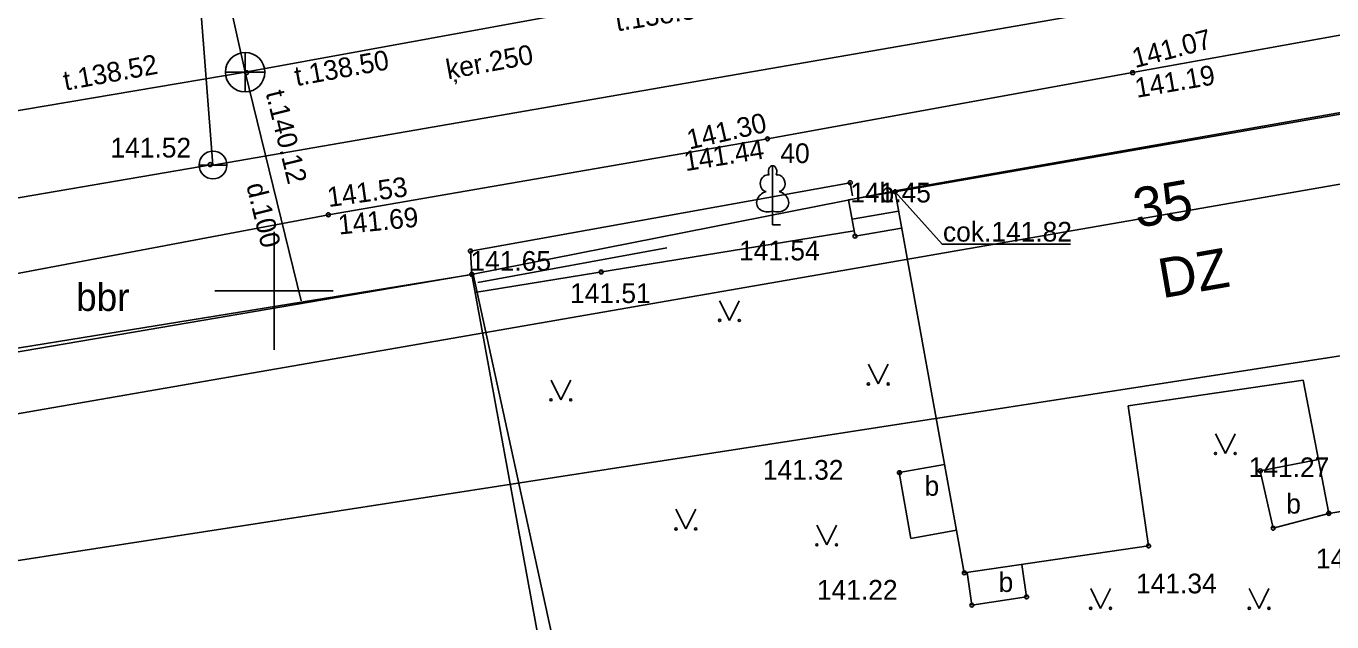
# Model space of a CAD drawing. Extents: x 728492 to 729038, y 272968 to 273171.
# Drawn here: x 728843.71 to 728876.83, y 273091.6 to 273106.71 of the extents above; entities that cross this region are included whole.
import ezdxf

# ---------------------------------------------------------------- set-up
doc = ezdxf.new("R2010")
doc.units = 0
for name, color, linetype in [('APGR_SARK_####_####_#', 7, 'Continuous'), ('BUVE_BDET_####_####_#', 7, 'Continuous'), ('BUVE_BDET_####_TKST_#', 7, 'Continuous'), ('BUVE_EKAS_####_####_#', 7, 'Continuous'), ('BUVE_EKAS_ADRS_TKST_#', 7, 'Continuous'), ('BUVE_EKAS_RAKS_TKST_#', 7, 'Continuous'), ('CELI_CAPM_####_####_#', 7, 'Continuous'), ('CELI_CMAL_####_####_#', 7, 'Continuous'), ('CELI_CSEG_####_TKST_#', 7, 'Continuous'), ('GEOD_ELEM_####_####_#', 7, 'Continuous'), ('NORB_ZOGS_ZSTP_####_#', 7, 'Continuous'), ('RAMI_UZMR_####_####_#', 7, 'Continuous'), ('RELJ_AATZ_####_TKST_#', 7, 'Continuous'), ('RELJ_ELEM_####_####_#', 7, 'Continuous'), ('ROBZ_UZMR_####_####_#', 7, 'Continuous'), ('SKAN_ELEM_####_####_#', 7, 'Continuous'), ('SKAN_VADP_PAST_####_#', 7, 'Continuous'), ('SKAN_VADP_PAST_TKST_#', 7, 'Continuous'), ('TERT_DIAM_####_TKST_#', 7, 'Continuous'), ('TERT_DZOG_####_####_#', 7, 'Continuous'), ('TERT_ELEM_####_####_#', 7, 'Continuous'), ('UDTK_ELEM_####_####_#', 7, 'Continuous'), ('UDTK_ELEM_####_TKST_#', 7, 'Continuous'), ('UDTK_VADP_UDEN_####_#', 7, 'Continuous')]:
    doc.layers.add(name, color=color, linetype=linetype)

msp = doc.modelspace()

# ---------------------------------------------------------------- linework, layer by layer
at = {"layer": 'APGR_SARK_####_####_#'}
msp.add_lwpolyline([(728964.826, 273117.961), (728827.017, 273094.024)], dxfattribs=at)
at = {"layer": 'BUVE_BDET_####_####_#'}
for p, q in [((728865.753, 273102.512), (728864.573, 273102.306)), ((728864.734, 273101.386), (728864.573, 273102.306)), ((728865.838, 273102.023), (728864.659, 273101.817)), ((728864.734, 273101.386), (728865.914, 273101.592)), ((728876.488, 273095.718), (728875.015, 273095.433)), ((728867.008, 273095.598), (728865.851, 273095.388)), ((728875.015, 273095.433), (728875.341, 273093.979)), ((728875.341, 273093.979), (728876.752, 273094.355)), ((728868.965, 273093.06), (728869.085, 273092.236)), ((728867.579, 273092.857), (728867.7, 273092.027)), ((728867.7, 273092.027), (728869.085, 273092.236))]:
    msp.add_line(p, q, dxfattribs=at)
for points in [[(728865.753, 273102.512), (728866.943, 273101.182), (728870.203, 273101.182)], [(728867.311, 273093.928), (728866.154, 273093.718), (728865.851, 273095.388)]]:
    msp.add_lwpolyline(points, dxfattribs=at)
at = {"layer": 'BUVE_EKAS_####_####_#'}
for p, q in [((728865.753, 273102.512), (728878.827, 273104.792)), ((728855.014, 273100.418), (728826.892, 273095.851)), ((728855.014, 273100.418), (728857.031, 273089.425)), ((728871.66, 273097.085), (728876.098, 273097.734)), ((728876.098, 273097.734), (728876.752, 273094.355)), ((728872.18, 273093.53), (728871.66, 273097.085))]:
    msp.add_line(p, q, dxfattribs=at)
for points in [[(728876.752, 273094.355), (728880.747, 273095.017), (728878.827, 273104.792)], [(728865.753, 273102.512), (728867.507, 273092.847), (728872.18, 273093.53)]]:
    msp.add_lwpolyline(points, dxfattribs=at)
at = {"layer": 'CELI_CAPM_####_####_#'}
msp.add_lwpolyline([(728921.451, 273114.43), (728906.807, 273111.886), (728887.177, 273108.316), (728871.777, 273105.534), (728862.513, 273103.854), (728851.375, 273101.928), (728832.719, 273098.413), (728826.071, 273097.316), (728825.017, 273097.001), (728824.765, 273096.832), (728824.532, 273096.455), (728824.532, 273096.455), (728826.161, 273084.877), (728827.609, 273074.269)], dxfattribs=at)
at = {"layer": 'CELI_CMAL_####_####_#'}
msp.add_lwpolyline([(728855.014, 273100.418), (728854.979, 273101.009), (728864.614, 273102.742), (728864.674, 273102.409)], dxfattribs=at)
at = {"layer": 'GEOD_ELEM_####_####_#'}
for p, q in [((728850, 273101.5), (728850, 273100)), ((728848.5, 273100), (728850, 273100)), ((728850, 273100), (728850, 273098.5)), ((728850, 273100), (728851.5, 273100))]:
    msp.add_line(p, q, dxfattribs=at)
at = {"layer": 'NORB_ZOGS_ZSTP_####_#'}
msp.add_lwpolyline([(728855.089, 273099.957), (728864.711, 273101.519)], dxfattribs=at)
at = {"layer": 'RAMI_UZMR_####_####_#'}
msp.add_lwpolyline([(728688.721, 273058.407), (728702.149, 273066.922), (728733.452, 273072.937), (728813.127, 273088.247), (728815.181, 273072.879), (728831.342, 273076.994), (728831.817, 273091.35), (728930.137, 273106.573), (728962.389, 273111.567), (728966.363, 273103.835), (728988.796, 273109.153), (728985.811, 273141.417), (728955.146, 273144.603), (728957.616, 273137.975), (728904.333, 273130.641), (728847.677, 273120.095), (728823.483, 273119.793), (728790.036, 273112.558), (728726.814, 273102.175), (728686.914, 273096.216)], dxfattribs=at)
at = {"layer": 'RELJ_ELEM_####_####_#'}
for centre in [(728849.299, 273105.533), (728871.777, 273105.534), (728862.513, 273103.854), (728848.376, 273103.201), (728864.614, 273102.742), (728865.753, 273102.512), (728851.375, 273101.928), (728864.734, 273101.386), (728854.979, 273101.009), (728855.014, 273100.418), (728858.295, 273100.478), (728865.862, 273095.388), (728875.015, 273095.433), (728876.752, 273094.355), (728875.341, 273093.979), (728872.18, 273093.53), (728867.507, 273092.847), (728867.7, 273092.027), (728869.085, 273092.236)]:
    msp.add_circle(centre, 0.05, dxfattribs=at)
at = {"layer": 'ROBZ_UZMR_####_####_#'}
for p, q in [((728865.791, 273102.548), (728878.892, 273104.843)), ((728855.048, 273100.425), (728865.791, 273102.548)), ((728826.945, 273095.617), (728855.048, 273100.425)), ((728855.048, 273100.425), (728859.365, 273080.687))]:
    msp.add_line(p, q, dxfattribs=at)
at = {"layer": 'SKAN_ELEM_####_####_#'}
for p, q in [((728849.263, 273105.046), (728849.263, 273106.046)), ((728848.763, 273105.546), (728849.763, 273105.546))]:
    msp.add_line(p, q, dxfattribs=at)
msp.add_circle((728849.263, 273105.546), 0.5, dxfattribs=at)
at = {"layer": 'SKAN_VADP_PAST_####_#'}
for points in [[(728849.263, 273105.546), (728846.52, 273117.868)], [(728849.263, 273105.546), (728861.79, 273107.84), (728860.538, 273115.361)], [(728835.266, 273103.178), (728849.263, 273105.546), (728850.688, 273099.748)]]:
    msp.add_lwpolyline(points, dxfattribs=at)
at = {"layer": 'TERT_DZOG_####_####_#'}
msp.add_lwpolyline([(728855.164, 273100.213), (728859.963, 273101.091)], dxfattribs=at)
at = {"layer": 'TERT_ELEM_####_####_#'}
for p, q in [((728862.645, 273102.021), (728862.645, 273101.674)), ((728862.645, 273102.021), (728862.645, 273101.674)), ((728862.645, 273101.674), (728862.845, 273101.674)), ((728862.645, 273101.674), (728862.845, 273101.674)), ((728861.3, 273099.749), (728861.55, 273099.249)), ((728861.55, 273099.249), (728861.8, 273099.749)), ((728865.074, 273098.137), (728865.324, 273097.637)), ((728865.324, 273097.637), (728865.574, 273098.137)), ((728857.024, 273097.735), (728857.274, 273097.235)), ((728857.274, 273097.235), (728857.524, 273097.735)), ((728873.879, 273096.375), (728874.129, 273095.875)), ((728874.129, 273095.875), (728874.379, 273096.375)), ((728860.193, 273094.461), (728860.443, 273093.961)), ((728860.443, 273093.961), (728860.693, 273094.461)), ((728863.766, 273094.058), (728864.016, 273093.558)), ((728864.016, 273093.558), (728864.266, 273094.058)), ((728870.713, 273092.446), (728870.963, 273091.946)), ((728870.963, 273091.946), (728871.213, 273092.446)), ((728874.734, 273092.446), (728874.984, 273091.946)), ((728874.984, 273091.946), (728875.234, 273092.446))]:
    msp.add_line(p, q, dxfattribs=at)
for points in [[(728862.645, 273103.174), (728862.645, 273102.021)], [(728862.645, 273103.174), (728862.645, 273102.021)], [(728862.735, 273102.942), (728862.734, 273102.943)], [(728862.735, 273102.942), (728862.734, 273102.943)]]:
    msp.add_lwpolyline(points, dxfattribs=at)
for centre, radius in [((728861.3, 273099.249), 0.028), ((728861.8, 273099.249), 0.0263), ((728865.074, 273097.637), 0.028), ((728865.574, 273097.637), 0.0263), ((728857.023, 273097.234), 0.028), ((728857.523, 273097.234), 0.0263), ((728873.878, 273095.874), 0.028), ((728874.378, 273095.874), 0.0263), ((728860.193, 273093.96), 0.028), ((728860.693, 273093.96), 0.0263), ((728863.765, 273093.558), 0.028), ((728864.265, 273093.558), 0.0263), ((728870.713, 273091.946), 0.028), ((728871.213, 273091.946), 0.0263), ((728874.734, 273091.946), 0.028), ((728875.234, 273091.946), 0.0263)]:
    msp.add_circle(centre, radius, dxfattribs=at)
for centre, major_axis, ratio, start_param, end_param in [((728862.517, 273102.729), (-0.039, -0.212), 0.861323, 3.141593, 6.283185), ((728862.517, 273102.729), (-0.039, -0.212), 0.861323, 3.141593, 6.283185), ((728862.645, 273103.024), (0, -0.15), 0.707107, 3.14537, 5.287485), ((728862.645, 273103.024), (0, -0.15), 0.707107, 3.14537, 5.287485), ((728862.645, 273103.024), (0, -0.15), 0.707107, 0.995701, 3.137816), ((728862.645, 273103.024), (0, -0.15), 0.707107, 0.995701, 3.137816), ((728862.773, 273102.729), (0.039, -0.212), 0.861323, 0, 3.141593), ((728862.773, 273102.729), (0.039, -0.212), 0.861323, 0, 3.141593), ((728862.555, 273102.267), (0.307, 0.095), 0.814445, 1.570796, 4.752015), ((728862.555, 273102.267), (0.307, 0.095), 0.814445, 1.570796, 4.752015), ((728862.735, 273102.267), (-0.307, 0.095), 0.814445, 1.531171, 4.712389), ((728862.735, 273102.267), (-0.307, 0.095), 0.814445, 1.531171, 4.712389)]:
    msp.add_ellipse(centre, major_axis=major_axis, ratio=ratio, start_param=start_param, end_param=end_param, dxfattribs=at)
at = {"layer": 'UDTK_ELEM_####_####_#'}
for p, q in [((728848.098, 273103.191), (728848.8, 273103.191)), ((728848.448, 273103.191), (728848.448, 273103.192))]:
    msp.add_line(p, q, dxfattribs=at)
msp.add_circle((728848.449, 273103.191), 0.351, dxfattribs=at)
at = {"layer": 'UDTK_VADP_UDEN_####_#'}
for p, q in [((728848.449, 273103.191), (728846.927, 273122.818)), ((728888.239, 273110.085), (728848.449, 273103.191)), ((728848.448, 273103.204), (728810.333, 273096.686))]:
    msp.add_line(p, q, dxfattribs=at)

# ---------------------------------------------------------------- texts
at = {"layer": 'BUVE_BDET_####_TKST_#'}
for s, p in [('b', (728865.357, 273102.239)), ('cok.141.82', (728866.965, 273101.249)), ('b', (728866.498, 273094.802)), ('b', (728875.674, 273094.35)), ('b', (728868.376, 273092.362))]:
    msp.add_text(s, height=0.5, dxfattribs=at).set_placement(p)
at = {"layer": 'BUVE_EKAS_ADRS_TKST_#'}
msp.add_text('35', height=1, rotation=9.893, dxfattribs=at).set_placement((728871.892, 273101.594))
at = {"layer": 'BUVE_EKAS_RAKS_TKST_#'}
msp.add_text('DZ', height=1, rotation=9.893, dxfattribs=at).set_placement((728872.527, 273099.809))
at = {"layer": 'CELI_CSEG_####_TKST_#'}
msp.add_text('bbr', height=0.7, dxfattribs=at).set_placement((728844.978, 273099.49))
at = {"layer": 'RELJ_AATZ_####_TKST_#'}
for s, rotation, p in [('141.07', 14.6324, (728871.838, 273105.647)), ('141.19', 9.7903, (728871.881, 273104.894)), ('141.30', 12.904, (728860.533, 273103.581)), ('141.44', 9.1698, (728860.437, 273103.033)), ('141.53', 7.8529, (728851.382, 273102.123)), ('141.69', 5.7153, (728851.645, 273101.426))]:
    msp.add_text(s, height=0.5, rotation=rotation, dxfattribs=at).set_placement(p)
for s, p in [('141.45', (728864.614, 273102.242)), ('141.65', (728854.979, 273100.509)), (' 141.54', (728861.606, 273100.773)), (' 141.51', (728857.321, 273099.69)), (' 141.32', (728862.211, 273095.209)), (' 141.27', (728874.533, 273095.274)), (' 141.23', (728876.24, 273092.961)), (' 141.34', (728871.678, 273092.327)), (' 141.22', (728863.583, 273092.166))]:
    msp.add_text(s, height=0.5, dxfattribs=at).set_placement(p)
at = {"layer": 'SKAN_VADP_PAST_TKST_#'}
for s, rotation, p in [('t.138.34', 9.257, (728858.698, 273106.579)), ('t.138.52', 10.377, (728844.702, 273105.077)), ('t.138.50', 10.377, (728850.568, 273105.189)), ('ķer.250', 10.377, (728854.409, 273105.361)), ('t.140.12', 283.808, (728849.781, 273105.022)), ('d.100', 283.808, (728849.29, 273102.677))]:
    msp.add_text(s, height=0.5, rotation=rotation, dxfattribs=at).set_placement(p)
at = {"layer": 'TERT_DIAM_####_TKST_#'}
msp.add_text('40', height=0.5, dxfattribs=at).set_placement((728862.841, 273103.24))
at = {"layer": 'UDTK_ELEM_####_TKST_#'}
msp.add_text('141.52', height=0.5, dxfattribs=at).set_placement((728845.849, 273103.381))

doc.saveas('drawing.dxf')
